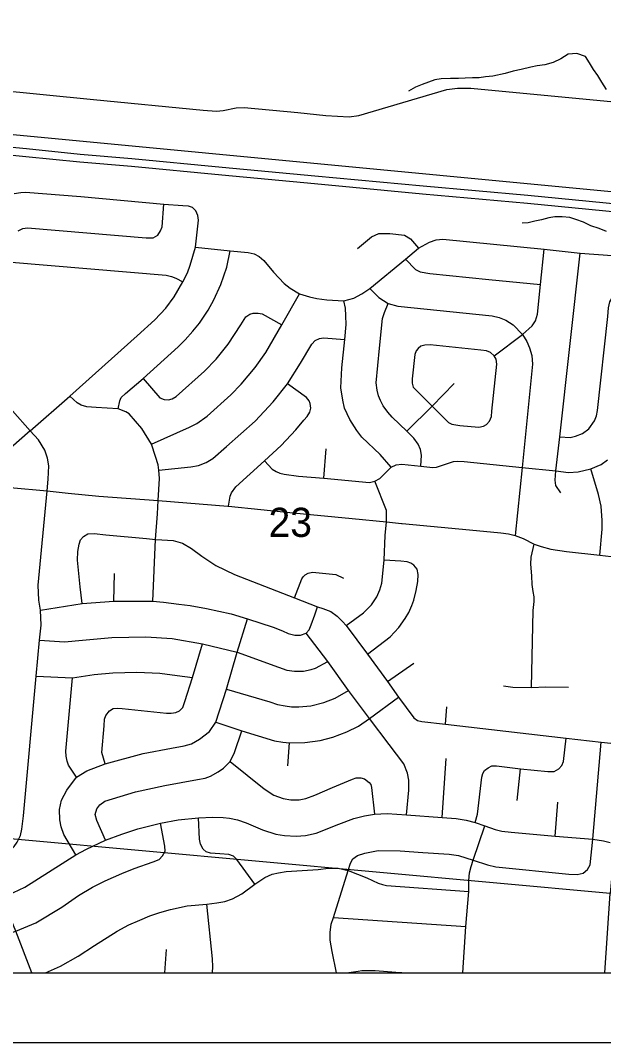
# Model space of a CAD drawing. Extents: x -38.1 to 35.9, y -2.7 to 28.5.
# Drawn here: x 11.979 to 12.816, y 12.831 to 14.299 of the extents above; entities that cross this region are included whole.
import ezdxf

# ---------------------------------------------------------------- set-up
doc = ezdxf.new("R2010")
doc.units = 0
for name, color, linetype in [('GM_X_City_Street', 7, 'Continuous'), ('GM_X_City_Street_Text', 7, 'Continuous'), ('GM_X_Corporation_Text', 7, 'Continuous'), ('GM_X_Minor_River', 7, 'Continuous'), ('GM_X_Section', 7, 'Continuous'), ('GM_X_US_Route', 7, 'Continuous'), ('SH_Border', 7, 'Continuous'), ('SH_Data', 7, 'Continuous')]:
    doc.layers.add(name, color=color, linetype=linetype)

msp = doc.modelspace()

# ---------------------------------------------------------------- linework, layer by layer
at = {"layer": 'GM_X_City_Street'}
for p, q in [((12.4146, 13.6416), (12.418, 13.6836)), ((12.1133, 13.4651), (12.1141, 13.5046)), ((12.5059, 13.3495), (12.5438, 13.3759)), ((12.5893, 13.2884), (12.5912, 13.3131)), ((12.3631, 13.2284), (12.3656, 13.2615)), ((12.5847, 13.1543), (12.5903, 13.2388)), ((12.6922, 13.1783), (12.6971, 13.2241)), ((12.7468, 13.1275), (12.7504, 13.176)), ((12.4288, 13.0106), (12.6187, 12.9973)), ((12.1864, 12.9308), (12.1887, 12.9643))]:
    msp.add_line(p, q, dxfattribs=at)
for points in [[(11.9391, 14.2002), (12.0843, 14.1854), (12.2415, 14.1701), (12.2607, 14.169), (12.2703, 14.1698), (12.2889, 14.1734), (12.3003, 14.1741), (12.3772, 14.1667), (12.4176, 14.1627), (12.4509, 14.1609), (12.4651, 14.1626), (12.5912, 14.1998), (12.6066, 14.2019), (12.6259, 14.2017), (12.9422, 14.1715)], [(11.97, 14.0504), (11.98, 14.0521), (11.9864, 14.0526), (12.0657, 14.0463), (12.185, 14.0353), (12.2122, 14.0334), (12.22, 14.0327), (12.2255, 14.0307)], [(11.9759, 13.9971), (11.9825, 14.0005), (11.9896, 14.0011), (12.1596, 13.9869), (12.1698, 13.987), (12.1763, 13.9906), (12.1805, 13.9969), (12.1825, 14.0028), (12.185, 14.0353)], [(11.9931, 13.7094), (12.0499, 13.7594), (12.1466, 13.8462), (12.1722, 13.8689), (12.1877, 13.8858), (12.1999, 13.9023), (12.2121, 13.9236), (12.2188, 13.9364), (12.2229, 13.9476), (12.2304, 13.9733), (12.2346, 14.0123), (12.234, 14.0191), (12.2309, 14.0258), (12.2255, 14.0307)], [(12.2304, 13.9733), (12.2802, 13.9681), (12.306, 13.9656), (12.3145, 13.964), (12.3221, 13.9599), (12.3287, 13.9543), (12.3423, 13.9374), (12.3577, 13.9212), (12.3666, 13.9144), (12.3799, 13.9066), (12.394, 13.902), (12.4046, 13.8995), (12.4192, 13.8978), (12.4436, 13.8965), (12.4578, 13.9004), (12.4692, 13.9063), (12.4808, 13.9143), (12.5322, 13.9564), (12.5505, 13.972), (12.5663, 13.9808), (12.576, 13.984), (12.5856, 13.9849), (12.7309, 13.9704), (12.7826, 13.965), (12.8815, 13.9577)], [(12.463, 13.9714), (12.4833, 13.9881), (12.4936, 13.9931), (12.5096, 13.993), (12.5304, 13.9905), (12.539, 13.9855), (12.5505, 13.972)], [(12.1197, 13.7414), (12.1221, 13.7527), (12.124, 13.7575), (12.13, 13.7633), (12.1554, 13.7849), (12.2055, 13.8303), (12.2158, 13.8405), (12.2267, 13.853), (12.2363, 13.8644), (12.2489, 13.883), (12.257, 13.8976), (12.2669, 13.9198), (12.2755, 13.9448), (12.2802, 13.9681)], [(12.6591, 13.8175), (12.6997, 13.8482), (12.7139, 13.8606), (12.7185, 13.8674), (12.7213, 13.8774), (12.7257, 13.9197), (12.7309, 13.9704)], [(12.7548, 13.6205), (12.7476, 13.6311), (12.7466, 13.6385), (12.748, 13.6522), (12.7536, 13.7012), (12.7826, 13.965)], [(11.9159, 13.9565), (11.9666, 13.9519), (12.1884, 13.933), (12.1963, 13.9311), (12.2022, 13.9287), (12.2121, 13.9236)], [(12.5322, 13.9564), (12.5462, 13.9414), (12.5531, 13.9378), (12.5668, 13.9355), (12.6514, 13.927), (12.7257, 13.9197)], [(12.1672, 13.6903), (12.2217, 13.7147), (12.2324, 13.7202), (12.2471, 13.7306), (12.2812, 13.7613), (12.296, 13.7764), (12.316, 13.8006), (12.3314, 13.8223), (12.3545, 13.862), (12.3799, 13.9066)], [(12.4808, 13.9143), (12.4939, 13.9012), (12.5072, 13.8924), (12.521, 13.8887), (12.6565, 13.8747), (12.6664, 13.8725), (12.6759, 13.8684), (12.6864, 13.8621), (12.6997, 13.8482), (12.706, 13.8379), (12.7098, 13.8287), (12.7132, 13.818), (12.7141, 13.8054), (12.7128, 13.7908), (12.6994, 13.6568), (12.6893, 13.559)], [(12.7536, 13.7012), (12.7684, 13.7002), (12.776, 13.7021), (12.7861, 13.7059), (12.7952, 13.7125), (12.8031, 13.724), (12.806, 13.731), (12.8076, 13.7389), (12.8223, 13.8737), (12.8235, 13.8864), (12.8251, 13.8949), (12.8285, 13.9006), (12.833, 13.9051), (12.8382, 13.908), (12.8431, 13.9094), (12.848, 13.9096), (12.857, 13.9088), (12.8756, 13.907)], [(12.5115, 13.6573), (12.4957, 13.6756), (12.4693, 13.7006), (12.462, 13.7103), (12.4522, 13.7257), (12.4446, 13.7421), (12.4421, 13.7537), (12.4393, 13.7714), (12.4406, 13.8002), (12.4448, 13.841), (12.4468, 13.8624), (12.4465, 13.8748), (12.4457, 13.8858), (12.4436, 13.8965)], [(12.5541, 13.6587), (12.555, 13.6748), (12.5537, 13.683), (12.5502, 13.6906), (12.544, 13.6989), (12.534, 13.7091), (12.513, 13.7293), (12.5065, 13.7364), (12.4998, 13.7454), (12.496, 13.7534), (12.4934, 13.76), (12.4912, 13.768), (12.4899, 13.7786), (12.4946, 13.8284), (12.4989, 13.8709), (12.5016, 13.8794), (12.5072, 13.8924)], [(12.1554, 13.7849), (12.1795, 13.7572), (12.1857, 13.7547), (12.1917, 13.7542), (12.1972, 13.7558), (12.2026, 13.7591), (12.2433, 13.7953), (12.2602, 13.8127), (12.2774, 13.8341), (12.2955, 13.8617), (12.3028, 13.8735), (12.3087, 13.8772), (12.3134, 13.8784), (12.3204, 13.8786), (12.3261, 13.8775), (12.3545, 13.862)], [(12.1781, 13.6529), (12.224, 13.6581), (12.2346, 13.6598), (12.2457, 13.664), (12.2556, 13.67), (12.2751, 13.6871), (12.3162, 13.7237), (12.342, 13.7514), (12.3628, 13.777), (12.3811, 13.8067), (12.3974, 13.8343), (12.4023, 13.8396), (12.4085, 13.8423), (12.4145, 13.8433), (12.4448, 13.841)], [(12.6591, 13.8175), (12.6538, 13.8222), (12.6481, 13.8246), (12.6403, 13.8253), (12.5674, 13.833), (12.5597, 13.8328), (12.5542, 13.8313), (12.5502, 13.828), (12.5472, 13.8243), (12.5454, 13.8192), (12.5414, 13.7841), (12.5414, 13.7781), (12.5432, 13.7724), (12.5704, 13.745)], [(12.5704, 13.745), (12.5939, 13.7218), (12.5986, 13.7191), (12.604, 13.718), (12.61, 13.7174), (12.637, 13.715), (12.6438, 13.7163), (12.6484, 13.7188), (12.6527, 13.7236), (12.6553, 13.7302), (12.6561, 13.738), (12.6631, 13.8055), (12.6621, 13.8124), (12.6591, 13.8175)], [(12.2781, 13.6012), (12.2802, 13.6157), (12.2824, 13.6207), (12.2885, 13.6291), (12.3296, 13.6665), (12.3533, 13.6886), (12.3744, 13.7109), (12.3862, 13.7251), (12.3909, 13.7303), (12.3945, 13.7365), (12.3963, 13.7423), (12.3951, 13.749), (12.3939, 13.7526), (12.3898, 13.7574), (12.3628, 13.777)], [(12.534, 13.7091), (12.5704, 13.745), (12.6017, 13.7778)], [(12.1691, 13.4651), (12.1732, 13.5537), (12.1761, 13.5904), (12.1769, 13.6095), (12.1788, 13.6411), (12.1781, 13.6529), (12.1767, 13.6607), (12.1732, 13.6727), (12.1672, 13.6903), (12.1535, 13.713), (12.1353, 13.7339), (12.1306, 13.7371), (12.1197, 13.7414), (12.088, 13.7433), (12.0747, 13.7441), (12.0662, 13.7464), (12.0607, 13.7496), (12.0499, 13.7594)], [(12.0175, 13.6234), (12.019, 13.6403), (12.0198, 13.6595), (12.018, 13.6701), (12.0141, 13.6817), (12.005, 13.6965), (11.9931, 13.7094), (11.9676, 13.7385)], [(11.9931, 13.7094), (11.9654, 13.685)], [(12.3296, 13.6665), (12.3408, 13.6546), (12.3461, 13.651), (12.3515, 13.6487), (12.3577, 13.6472), (12.3785, 13.6446), (12.4146, 13.6416), (12.4801, 13.6356), (12.4881, 13.6374), (12.495, 13.6413), (12.5115, 13.6573), (12.5184, 13.6608), (12.5265, 13.6617), (12.5541, 13.6587), (12.5712, 13.6571), (12.5763, 13.6573), (12.6009, 13.6653), (12.6072, 13.666), (12.6162, 13.6653), (12.6994, 13.6568), (12.748, 13.6522), (12.7661, 13.6498), (12.7797, 13.6507), (12.798, 13.655), (12.8129, 13.6614), (12.8221, 13.668)], [(12.8111, 13.531), (12.8144, 13.5681), (12.8144, 13.581), (12.8128, 13.6016), (12.8092, 13.6181), (12.798, 13.655)], [(12.4466, 13.43), (12.4717, 13.448), (12.4833, 13.4596), (12.491, 13.4712), (12.4951, 13.4812), (12.4982, 13.4908), (12.5012, 13.5236), (12.5029, 13.5594), (12.5045, 13.5788), (12.5047, 13.5859), (12.5045, 13.5949), (12.4881, 13.6374)], [(11.9955, 12.9308), (11.9724, 12.9907), (11.9531, 13.0387), (11.946, 13.0576), (11.9442, 13.0643), (11.9438, 13.07), (11.9446, 13.0768), (11.9465, 13.0841), (11.9502, 13.0911), (11.9597, 13.1016), (11.9704, 13.1126), (11.9747, 13.1188), (11.9791, 13.1281), (11.9814, 13.1373), (11.9837, 13.1566), (12.002, 13.3571), (12.0068, 13.409), (12.0088, 13.4306), (12.0079, 13.4518), (12.0055, 13.4665), (12.0045, 13.4878), (12.0175, 13.6234)], [(12.0677, 13.4616), (12.0648, 13.4853), (12.061, 13.5236), (12.0616, 13.5362), (12.0634, 13.547), (12.0654, 13.5529), (12.0697, 13.5576), (12.0758, 13.5615), (12.0852, 13.5623), (12.1017, 13.5604), (12.1604, 13.5549), (12.1732, 13.5537), (12.182, 13.5531), (12.1983, 13.5521), (12.2119, 13.548), (12.225, 13.5405), (12.2396, 13.5297), (12.2599, 13.5162), (12.2867, 13.5032), (12.3727, 13.4698), (12.4057, 13.4569), (12.4132, 13.4543), (12.4246, 13.4498), (12.434, 13.4433), (12.4413, 13.4358), (12.4466, 13.43), (12.4772, 13.3887), (12.5059, 13.3495), (12.522, 13.327), (12.5439, 13.2971), (12.5492, 13.2936), (12.5554, 13.2919), (12.5893, 13.2884), (12.7627, 13.268), (12.8128, 13.2625), (12.8637, 13.257)], [(12.7128, 13.3409), (12.7153, 13.4515), (12.7169, 13.4645), (12.7169, 13.471), (12.7153, 13.479), (12.7137, 13.4888), (12.7131, 13.5012), (12.7119, 13.5181), (12.7123, 13.528), (12.7166, 13.5468)], [(12.4772, 13.3887), (12.5098, 13.4135), (12.5226, 13.427), (12.5314, 13.4398), (12.5367, 13.4488), (12.541, 13.4588), (12.5438, 13.4661), (12.5475, 13.4802), (12.5497, 13.493), (12.5503, 13.503), (12.5485, 13.5109), (12.5438, 13.5168), (12.5395, 13.5195), (12.5342, 13.5213), (12.5251, 13.5223), (12.5012, 13.5236)], [(12.3727, 13.4698), (12.3833, 13.4969), (12.3851, 13.4997), (12.388, 13.5026), (12.3924, 13.505), (12.3985, 13.5064), (12.4318, 13.5032), (12.4428, 13.4977)], [(12.0079, 13.4518), (12.0677, 13.4616), (12.1133, 13.4651), (12.1691, 13.4651), (12.1848, 13.4635), (12.2066, 13.4608), (12.2231, 13.4586), (12.2464, 13.4543), (12.2816, 13.4465), (12.3052, 13.4394), (12.3421, 13.4274), (12.3554, 13.4221), (12.3637, 13.4182), (12.3733, 13.416), (12.3812, 13.416), (12.3892, 13.419), (12.3937, 13.4239), (12.3967, 13.4311), (12.4016, 13.4453), (12.4057, 13.4569)], [(12.0587, 13.1003), (12.0417, 13.1296), (12.0375, 13.1406), (12.0359, 13.1509), (12.0355, 13.1655), (12.0381, 13.1789), (12.0457, 13.1935), (12.0597, 13.2122), (12.0745, 13.2213), (12.1007, 13.2314), (12.1555, 13.246), (12.196, 13.2536), (12.2142, 13.257), (12.2247, 13.2601), (12.2362, 13.2664), (12.2505, 13.2777), (12.2597, 13.2909), (12.275, 13.3384), (12.2905, 13.3916), (12.3052, 13.4394)], [(12.0068, 13.409), (12.0426, 13.4064), (12.0684, 13.4089), (12.1104, 13.4127), (12.1593, 13.4136), (12.1972, 13.4111), (12.2407, 13.4037), (12.2905, 13.3916), (12.3499, 13.3701), (12.3617, 13.3658), (12.3727, 13.3642), (12.3855, 13.3645), (12.3964, 13.3668), (12.403, 13.3688), (12.4203, 13.3781)], [(12.5336, 13.1581), (12.5367, 13.1934), (12.5369, 13.2076), (12.5348, 13.2177), (12.5294, 13.231), (12.5084, 13.2591), (12.4805, 13.2965), (12.4503, 13.3367), (12.4203, 13.3781), (12.3892, 13.419)], [(12.1007, 13.2314), (12.0962, 13.2475), (12.0992, 13.2858), (12.0997, 13.2953), (12.1017, 13.3008), (12.1072, 13.3074), (12.1125, 13.3105), (12.1179, 13.3113), (12.1252, 13.3107), (12.1889, 13.3042), (12.1955, 13.3038), (12.2022, 13.305), (12.2075, 13.3075), (12.2121, 13.3119), (12.2154, 13.3205), (12.2261, 13.3551), (12.2407, 13.4037)], [(12.002, 13.3571), (12.0541, 13.3549), (12.0852, 13.3596), (12.1117, 13.3619), (12.1464, 13.3627), (12.1791, 13.3615), (12.2044, 13.3582), (12.2261, 13.3551)], [(12.0597, 13.2122), (12.0484, 13.2291), (12.0461, 13.2352), (12.0449, 13.2422), (12.0444, 13.2495), (12.0541, 13.3549)], [(12.275, 13.3384), (12.3372, 13.3201), (12.3483, 13.3166), (12.3591, 13.3145), (12.3682, 13.3133), (12.3787, 13.3129), (12.3963, 13.3147), (12.4148, 13.3192), (12.4309, 13.3257), (12.4503, 13.3367)], [(12.6728, 13.3433), (12.6859, 13.3413), (12.7128, 13.3409), (12.7333, 13.3419), (12.766, 13.3411)], [(12.2597, 13.2909), (12.297, 13.2786), (12.3441, 13.2644), (12.3558, 13.2623), (12.3656, 13.2615), (12.3874, 13.2619), (12.4096, 13.2646), (12.4278, 13.2695), (12.4479, 13.2771), (12.4643, 13.2852), (12.4805, 13.2965), (12.522, 13.327)], [(12.1014, 13.1214), (12.0889, 13.15), (12.0864, 13.1584), (12.0887, 13.1663), (12.093, 13.1723), (12.1003, 13.1774), (12.1446, 13.1909), (12.1863, 13.1999), (12.2333, 13.2088), (12.2444, 13.2108), (12.2522, 13.2137), (12.2631, 13.2198), (12.2706, 13.2251), (12.2801, 13.2345), (12.2863, 13.2474), (12.297, 13.2786)], [(12.4331, 12.9308), (12.4269, 12.9616), (12.4239, 12.9779), (12.4237, 12.9891), (12.4255, 13.0009), (12.4288, 13.0106), (12.4496, 13.0781), (12.4528, 13.0884), (12.4566, 13.0949), (12.4629, 13.0993), (12.4738, 13.103), (12.4926, 13.1069), (12.5241, 13.1061), (12.5567, 13.1039), (12.5946, 13.1015), (12.6079, 13.0996), (12.629, 13.0929), (12.6496, 13.0859), (12.6617, 13.0832), (12.7663, 13.0729), (12.7785, 13.0724), (12.787, 13.074), (12.7933, 13.0793), (12.7969, 13.0861), (12.8007, 13.1229), (12.8128, 13.2625)], [(12.6322, 13.1468), (12.6352, 13.1589), (12.6417, 13.212), (12.643, 13.2172), (12.6456, 13.2215), (12.6506, 13.2255), (12.6561, 13.2282), (12.6624, 13.2284), (12.6971, 13.2241), (12.7364, 13.2201), (12.7455, 13.2202), (12.752, 13.2238), (12.7562, 13.2286), (12.759, 13.2347), (12.7627, 13.268)], [(12.2801, 13.2345), (12.3292, 13.1953), (12.3432, 13.186), (12.3563, 13.1813), (12.3673, 13.1796), (12.3795, 13.1793), (12.3891, 13.1812), (12.4018, 13.186), (12.427, 13.1973), (12.456, 13.2093), (12.4612, 13.2111), (12.4678, 13.2113), (12.4732, 13.2096), (12.4799, 13.2044), (12.482, 13.2013), (12.4831, 13.1974), (12.4873, 13.1588)], [(11.9531, 13.0387), (11.9857, 13.0541), (12.0587, 13.1003), (12.074, 13.1084), (12.1014, 13.1214), (12.1246, 13.1301), (12.1477, 13.1376), (12.1801, 13.146), (12.2055, 13.1506), (12.2349, 13.1534), (12.2553, 13.1547), (12.2703, 13.1543), (12.2795, 13.1532), (12.2906, 13.1509), (12.3033, 13.1465), (12.3267, 13.1365), (12.3458, 13.13), (12.3582, 13.1281), (12.375, 13.1272), (12.3885, 13.1284), (12.4035, 13.1318), (12.4363, 13.1446), (12.4576, 13.1527), (12.4729, 13.1567), (12.4873, 13.1588), (12.5057, 13.1596), (12.5336, 13.1581), (12.5847, 13.1543), (12.6045, 13.1526), (12.6189, 13.1504), (12.6322, 13.1468), (12.6459, 13.142), (12.6609, 13.1368), (12.6704, 13.1345), (12.6835, 13.1329), (12.7468, 13.1275), (12.8007, 13.1229), (12.8162, 13.1208), (12.8257, 13.1183)], [(11.8867, 12.97), (11.9241, 12.9757), (11.9305, 12.977), (11.9724, 12.9907), (12.0012, 13.0028), (12.0388, 13.0254), (12.0627, 13.0418), (12.0827, 13.054), (12.1007, 13.0633), (12.1248, 13.0738), (12.1423, 13.081), (12.1696, 13.0902), (12.1786, 13.0937), (12.1832, 13.0991), (12.1868, 13.1056), (12.1863, 13.1129), (12.1801, 13.146)], [(12.3159, 13.0582), (12.2898, 13.0936), (12.2849, 13.0985), (12.2782, 13.101), (12.2654, 13.1018), (12.2519, 13.1029), (12.246, 13.1049), (12.2416, 13.1086), (12.2377, 13.1157), (12.2363, 13.123), (12.2349, 13.1534)], [(12.6141, 12.9308), (12.6187, 12.9973), (12.6227, 13.0479), (12.623, 13.0634), (12.624, 13.0746), (12.6261, 13.0837), (12.629, 13.0929), (12.6459, 13.142)], [(12.0151, 12.9308), (12.0366, 12.9407), (12.0621, 12.955), (12.0856, 12.9703), (12.1182, 12.991), (12.1348, 12.9998), (12.1504, 13.0068), (12.1651, 13.0129), (12.1794, 13.0174), (12.1948, 13.0219), (12.2187, 13.027), (12.2466, 13.0298), (12.261, 13.0313), (12.2728, 13.0333), (12.2836, 13.0371), (12.297, 13.0444), (12.3159, 13.0582), (12.3302, 13.068), (12.3406, 13.0725), (12.3499, 13.0748), (12.3606, 13.0763), (12.4065, 13.0796), (12.4216, 13.0811), (12.4352, 13.0814), (12.4496, 13.0781), (12.4764, 13.0672), (12.4928, 13.0597), (12.4989, 13.0577), (12.5047, 13.0564), (12.6227, 13.0479)], [(12.2549, 12.9308), (12.2551, 12.9313), (12.2554, 12.9394), (12.2548, 12.951), (12.2466, 13.0298)], [(12.4475, 12.9308), (12.4638, 12.9333), (12.4692, 12.9341), (12.4883, 12.9341), (12.518, 12.932), (12.5358, 12.9308)]]:
    msp.add_lwpolyline(points, dxfattribs=at)
at = {"layer": 'GM_X_City_Street_Text'}
for p, q in [((12.0175, 13.6234), (12.0476, 13.6202)), ((12.1769, 13.6095), (12.2771, 13.6013))]:
    msp.add_line(p, q, dxfattribs=at)
for points in [[(11.8799, 13.6361), (11.8869, 13.6355), (11.9646, 13.6281), (12.0175, 13.6234)], [(12.0476, 13.6202), (12.0917, 13.6157), (12.1769, 13.6095)], [(12.2771, 13.6013), (12.2781, 13.6012), (12.3708, 13.592), (12.4556, 13.5837), (12.5045, 13.5788), (12.5263, 13.5766)], [(12.5263, 13.5766), (12.5273, 13.5765), (12.6239, 13.5675), (12.6688, 13.563), (12.6799, 13.5614), (12.6893, 13.559), (12.7007, 13.5549), (12.7166, 13.5468), (12.7266, 13.5433), (12.7408, 13.5397), (12.763, 13.5364), (12.8111, 13.531), (12.8598, 13.5254), (12.8842, 13.5237), (12.9024, 13.5227), (12.9383, 13.5205), (13.0075, 13.5158), (13.0454, 13.5128), (13.1416, 13.5061)]]:
    msp.add_lwpolyline(points, dxfattribs=at)
at = {"layer": 'GM_X_Corporation_Text'}
for points in [[(11.398, 14.1583), (11.4008, 14.158), (11.4217, 14.1558), (11.5171, 14.1477), (11.5805, 14.1423), (11.5955, 14.1407), (11.7065, 14.1289), (11.8164, 14.1195), (11.9059, 14.1118), (11.9871, 14.1039), (12.0643, 14.096), (12.1385, 14.0897), (12.2683, 14.0774), (12.4013, 14.0647), (12.5566, 14.0502), (12.707, 14.0369), (12.8391, 14.0238), (12.9932, 14.0104), (13.1057, 14.0001), (13.1867, 13.9931), (13.3126, 13.9816), (13.3638, 13.9765)], [(11.9065, 14.123), (11.9878, 14.1151), (12.0649, 14.1072), (12.1391, 14.1009), (12.2689, 14.0886), (12.402, 14.0759), (12.5572, 14.0614), (12.7076, 14.0481), (12.8397, 14.035), (12.9938, 14.0216), (13.1063, 14.0113), (13.1873, 14.0043), (13.3347, 13.9909), (13.3776, 13.9872), (13.3982, 13.9853), (13.5181, 13.9733), (13.5415, 13.971), (13.7615, 13.9529)]]:
    msp.add_lwpolyline(points, dxfattribs=at)
at = {"layer": 'GM_X_Section'}
for points in [[(12.8204, 14.1999), (12.8138, 14.2107), (12.8079, 14.2199), (12.8016, 14.2288), (12.7961, 14.2384), (12.7902, 14.2473), (12.7778, 14.2517), (12.7656, 14.2508), (12.7549, 14.2438), (12.7441, 14.2387), (12.7319, 14.2355), (12.7209, 14.2338), (12.7121, 14.2321), (12.698, 14.2286), (12.6866, 14.2261), (12.6748, 14.2229), (12.6572, 14.2191), (12.647, 14.2182), (12.6378, 14.2168), (12.6283, 14.2166), (12.6177, 14.2161), (12.6082, 14.2159), (12.5964, 14.2158), (12.5831, 14.2153), (12.574, 14.2139), (12.5648, 14.2107), (12.5557, 14.2071), (12.5465, 14.2034), (12.5361, 14.1976)], [(12.8204, 13.9962), (12.8102, 14.0002), (12.7978, 14.0042), (12.7876, 14.0094), (12.7767, 14.0134), (12.768, 14.0159), (12.7567, 14.0172), (12.7464, 14.017), (12.7377, 14.0157), (12.727, 14.0129), (12.7175, 14.0108), (12.7079, 14.0083), (12.6994, 14.0078)]]:
    msp.add_lwpolyline(points, dxfattribs=at)
at = {"layer": 'GM_X_US_Route'}
for points in [[(8.1146, 17.8763), (8.1146, 12.9308), (14.9146, 12.9308)], [(9.4553, 12.9308), (14.9146, 12.9308)], [(10.245, 12.9308), (14.9146, 12.9308)]]:
    msp.add_lwpolyline(points, dxfattribs=at)
for points in [[(12.9176, 14.045), (12.826, 13.0449), (11.8177, 13.1367), (11.9082, 14.1412)], [(11.8039, 12.9308), (12.8181, 12.9308), (12.826, 13.0449), (11.8177, 13.1367)]]:
    msp.add_lwpolyline(points, close=True, dxfattribs=at)
at = {"layer": 'SH_Border'}
msp.add_line((8.1146, 12.9308), (14.9146, 12.9308), dxfattribs=at)
at = {"layer": 'SH_Data'}
msp.add_line((8.0146, 12.8308), (15.0146, 12.8308), dxfattribs=at)

# ---------------------------------------------------------------- texts
at = {"layer": 'GM_X_Minor_River'}
msp.add_text('23', height=0.04186, rotation=0, dxfattribs=at).set_placement((12.3354, 13.5572))

doc.saveas('drawing.dxf')
